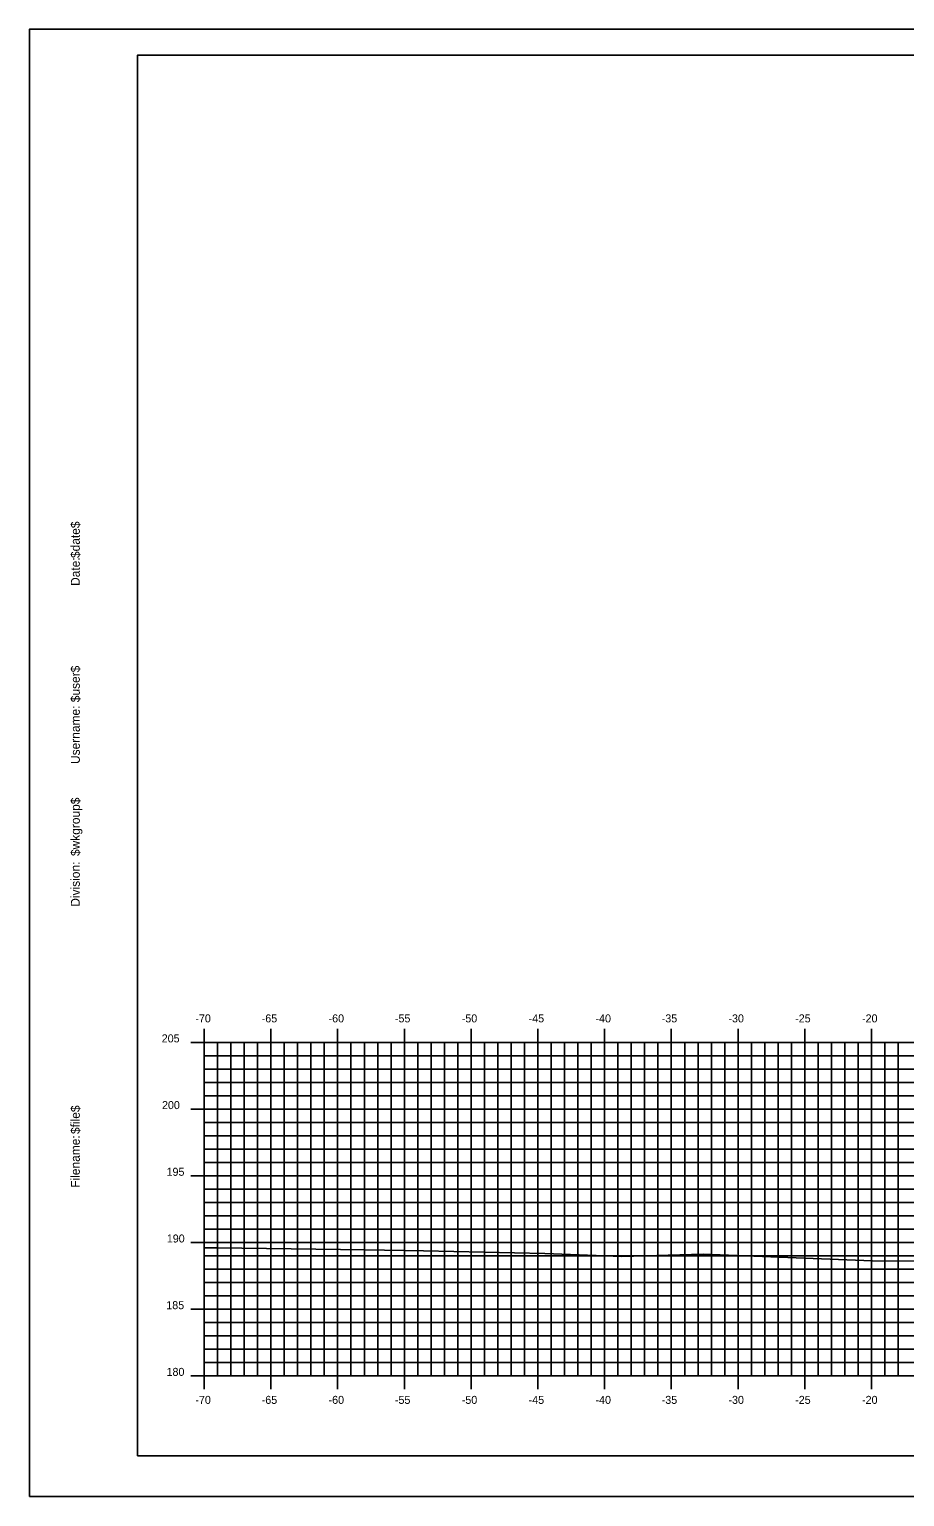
# Model space of a CAD drawing. Extents: x 1724208 to 1724380, y 458501 to 458611.
# Drawn here: x 1724208 to 1724273.5, y 458501.2 to 458611.2 of the extents above; entities that cross this region are included whole.
import ezdxf

# ---------------------------------------------------------------- set-up
doc = ezdxf.new("R2010")
doc.units = 0
for name, color, linetype in [('BORDER', 7, 'Continuous'), ('H_V ANNOTATION', 7, 'Continuous'), ('MAJOR', 7, 'Continuous'), ('MINOR', 7, 'Continuous'), ('PLOT BOUNDARY', 7, 'Continuous'), ('S_Roadway_Centerline', 7, 'Continuous')]:
    doc.layers.add(name, color=color, linetype=linetype)

msp = doc.modelspace()

# ---------------------------------------------------------------- linework, layer by layer
at = {"layer": 'BORDER'}
msp.add_lwpolyline([(1724216.06, 458504.25), (1724376.06, 458504.25), (1724376.06, 458609.25), (1724216.06, 458609.25)], close=True, dxfattribs=at)
at = {"layer": 'MAJOR'}
for p, q in [((1724221.06, 458536.26), (1724221.06, 458535.25)), ((1724226.06, 458536.26), (1724226.06, 458535.25)), ((1724231.06, 458536.26), (1724231.06, 458535.25)), ((1724236.06, 458536.26), (1724236.06, 458535.25)), ((1724241.06, 458536.26), (1724241.06, 458535.25)), ((1724246.06, 458536.26), (1724246.06, 458535.25)), ((1724251.06, 458536.26), (1724251.06, 458535.25)), ((1724256.06, 458536.26), (1724256.06, 458535.25)), ((1724261.06, 458536.26), (1724261.06, 458535.25)), ((1724266.06, 458536.26), (1724266.06, 458535.25)), ((1724271.06, 458536.26), (1724271.06, 458535.25)), ((1724220.05, 458535.25), (1724221.06, 458535.25)), ((1724221.06, 458535.25), (1724361.06, 458535.25)), ((1724221.06, 458510.25), (1724221.06, 458535.25)), ((1724221.06, 458510.25), (1724221.06, 458535.25)), ((1724221.06, 458535.25), (1724361.06, 458535.25)), ((1724226.06, 458510.25), (1724226.06, 458535.25)), ((1724231.06, 458510.25), (1724231.06, 458535.25)), ((1724236.06, 458510.25), (1724236.06, 458535.25)), ((1724241.06, 458510.25), (1724241.06, 458535.25)), ((1724246.06, 458510.25), (1724246.06, 458535.25)), ((1724251.06, 458510.25), (1724251.06, 458535.25)), ((1724256.06, 458510.25), (1724256.06, 458535.25)), ((1724261.06, 458510.25), (1724261.06, 458535.25)), ((1724266.06, 458510.25), (1724266.06, 458535.25)), ((1724271.06, 458510.25), (1724271.06, 458535.25)), ((1724220.05, 458530.25), (1724221.06, 458530.25)), ((1724221.06, 458530.25), (1724361.06, 458530.25)), ((1724220.05, 458525.25), (1724221.06, 458525.25)), ((1724221.06, 458525.25), (1724361.06, 458525.25)), ((1724220.05, 458520.25), (1724221.06, 458520.25)), ((1724221.06, 458520.25), (1724361.06, 458520.25)), ((1724220.05, 458515.25), (1724221.06, 458515.25)), ((1724221.06, 458515.25), (1724361.06, 458515.25)), ((1724220.05, 458510.25), (1724221.06, 458510.25)), ((1724221.06, 458510.25), (1724361.06, 458510.25)), ((1724221.06, 458510.25), (1724361.06, 458510.25)), ((1724221.06, 458509.25), (1724221.06, 458510.25)), ((1724226.06, 458509.25), (1724226.06, 458510.25)), ((1724231.06, 458509.25), (1724231.06, 458510.25)), ((1724236.06, 458509.25), (1724236.06, 458510.25)), ((1724241.06, 458509.25), (1724241.06, 458510.25)), ((1724246.06, 458509.25), (1724246.06, 458510.25)), ((1724251.06, 458509.25), (1724251.06, 458510.25)), ((1724256.06, 458509.25), (1724256.06, 458510.25)), ((1724261.06, 458509.25), (1724261.06, 458510.25)), ((1724266.06, 458509.25), (1724266.06, 458510.25)), ((1724271.06, 458509.25), (1724271.06, 458510.25))]:
    msp.add_line(p, q, dxfattribs=at)
at = {"layer": 'MINOR'}
for p, q in [((1724222.06, 458510.25), (1724222.06, 458535.25)), ((1724223.06, 458510.25), (1724223.06, 458535.25)), ((1724224.06, 458510.25), (1724224.06, 458535.25)), ((1724225.06, 458510.25), (1724225.06, 458535.25)), ((1724227.06, 458510.25), (1724227.06, 458535.25)), ((1724228.06, 458510.25), (1724228.06, 458535.25)), ((1724229.06, 458510.25), (1724229.06, 458535.25)), ((1724230.06, 458510.25), (1724230.06, 458535.25)), ((1724232.06, 458510.25), (1724232.06, 458535.25)), ((1724233.06, 458510.25), (1724233.06, 458535.25)), ((1724234.06, 458510.25), (1724234.06, 458535.25)), ((1724235.06, 458510.25), (1724235.06, 458535.25)), ((1724237.06, 458510.25), (1724237.06, 458535.25)), ((1724238.06, 458510.25), (1724238.06, 458535.25)), ((1724239.06, 458510.25), (1724239.06, 458535.25)), ((1724240.06, 458510.25), (1724240.06, 458535.25)), ((1724242.06, 458510.25), (1724242.06, 458535.25)), ((1724243.06, 458510.25), (1724243.06, 458535.25)), ((1724244.06, 458510.25), (1724244.06, 458535.25)), ((1724245.06, 458510.25), (1724245.06, 458535.25)), ((1724247.06, 458510.25), (1724247.06, 458535.25)), ((1724248.06, 458510.25), (1724248.06, 458535.25)), ((1724249.06, 458510.25), (1724249.06, 458535.25)), ((1724250.06, 458510.25), (1724250.06, 458535.25)), ((1724252.06, 458510.25), (1724252.06, 458535.25)), ((1724253.06, 458510.25), (1724253.06, 458535.25)), ((1724254.06, 458510.25), (1724254.06, 458535.25)), ((1724255.06, 458510.25), (1724255.06, 458535.25)), ((1724257.06, 458510.25), (1724257.06, 458535.25)), ((1724258.06, 458510.25), (1724258.06, 458535.25)), ((1724259.06, 458510.25), (1724259.06, 458535.25)), ((1724260.06, 458510.25), (1724260.06, 458535.25)), ((1724262.06, 458510.25), (1724262.06, 458535.25)), ((1724263.06, 458510.25), (1724263.06, 458535.25)), ((1724264.06, 458510.25), (1724264.06, 458535.25)), ((1724265.06, 458510.25), (1724265.06, 458535.25)), ((1724267.06, 458510.25), (1724267.06, 458535.25)), ((1724268.06, 458510.25), (1724268.06, 458535.25)), ((1724269.06, 458510.25), (1724269.06, 458535.25)), ((1724270.06, 458510.25), (1724270.06, 458535.25)), ((1724272.06, 458510.25), (1724272.06, 458535.25)), ((1724273.06, 458510.25), (1724273.06, 458535.25)), ((1724221.06, 458534.25), (1724361.06, 458534.25)), ((1724221.06, 458534.25), (1724222.06, 458534.25)), ((1724221.06, 458533.25), (1724361.06, 458533.25)), ((1724221.06, 458533.25), (1724222.06, 458533.25)), ((1724221.06, 458532.25), (1724361.06, 458532.25)), ((1724221.06, 458532.25), (1724222.06, 458532.25)), ((1724221.06, 458531.25), (1724361.06, 458531.25)), ((1724221.06, 458531.25), (1724222.06, 458531.25)), ((1724221.06, 458529.25), (1724361.06, 458529.25)), ((1724221.06, 458529.25), (1724222.06, 458529.25)), ((1724221.06, 458528.25), (1724361.06, 458528.25)), ((1724221.06, 458528.25), (1724222.06, 458528.25)), ((1724221.06, 458527.25), (1724361.06, 458527.25)), ((1724221.06, 458527.25), (1724222.06, 458527.25)), ((1724221.06, 458526.25), (1724361.06, 458526.25)), ((1724221.06, 458526.25), (1724222.06, 458526.25)), ((1724221.06, 458524.25), (1724361.06, 458524.25)), ((1724221.06, 458524.25), (1724222.06, 458524.25)), ((1724221.06, 458523.25), (1724361.06, 458523.25)), ((1724221.06, 458523.25), (1724222.06, 458523.25)), ((1724221.06, 458522.25), (1724361.06, 458522.25)), ((1724221.06, 458522.25), (1724222.06, 458522.25)), ((1724221.06, 458521.25), (1724361.06, 458521.25)), ((1724221.06, 458521.25), (1724222.06, 458521.25)), ((1724221.06, 458519.25), (1724361.06, 458519.25)), ((1724221.06, 458519.25), (1724222.06, 458519.25)), ((1724221.06, 458518.25), (1724361.06, 458518.25)), ((1724221.06, 458518.25), (1724222.06, 458518.25)), ((1724221.06, 458517.25), (1724361.06, 458517.25)), ((1724221.06, 458517.25), (1724222.06, 458517.25)), ((1724221.06, 458516.25), (1724361.06, 458516.25)), ((1724221.06, 458516.25), (1724222.06, 458516.25)), ((1724221.06, 458514.25), (1724361.06, 458514.25)), ((1724221.06, 458514.25), (1724222.06, 458514.25)), ((1724221.06, 458513.25), (1724361.06, 458513.25)), ((1724221.06, 458513.25), (1724222.06, 458513.25)), ((1724221.06, 458512.25), (1724361.06, 458512.25)), ((1724221.06, 458512.25), (1724222.06, 458512.25)), ((1724221.06, 458511.25), (1724361.06, 458511.25)), ((1724221.06, 458511.25), (1724222.06, 458511.25))]:
    msp.add_line(p, q, dxfattribs=at)
at = {"layer": 'PLOT BOUNDARY'}
msp.add_lwpolyline([(1724207.96, 458501.2), (1724377.96, 458501.2), (1724377.96, 458611.2), (1724207.96, 458611.2)], close=True, dxfattribs=at)
at = {"layer": 'S_Roadway_Centerline'}
msp.add_lwpolyline([(1724221.06, 458519.86), (1724222.04, 458519.84), (1724233.13, 458519.69), (1724237.5, 458519.63), (1724246.58, 458519.43), (1724252.36, 458519.21), (1724258.45, 458519.37), (1724270.48, 458518.9), (1724271.14, 458518.87), (1724282.01, 458518.79), (1724290.27, 458518.46), (1724306.73, 458518.2), (1724309.81, 458518.04), (1724318.6, 458517.35), (1724329.26, 458517.2), (1724343.8, 458516.42), (1724348.79, 458516.23), (1724361.06, 458515.7)], dxfattribs=at)

# ---------------------------------------------------------------- texts
at = {"layer": 'BORDER'}
for s, p in [('$date$', (1724211.74, 458571.56)), ('Date:', (1724211.74, 458569.47)), ('$user$', (1724211.74, 458560.75)), ('Username:', (1724211.74, 458556.12)), ('$wkgroup$', (1724211.74, 458549.22)), ('Division:', (1724211.74, 458545.42)), ('$file$', (1724211.74, 458528.38)), ('Filename:', (1724211.74, 458524.35))]:
    msp.add_text(s, height=0.67, rotation=90, dxfattribs=at).set_placement(p)
at = {"layer": 'H_V ANNOTATION'}
for s, p in [('-70', (1724220.4, 458536.75)), ('-65', (1724225.37, 458536.75)), ('-60', (1724230.38, 458536.75)), ('-55', (1724235.35, 458536.75)), ('-50', (1724240.36, 458536.75)), ('-45', (1724245.37, 458536.75)), ('-40', (1724250.38, 458536.75)), ('-35', (1724255.34, 458536.75)), ('-30', (1724260.34, 458536.75)), ('-25', (1724265.34, 458536.75)), ('-20', (1724270.35, 458536.75)), ('205', (1724217.88, 458535.25)), ('200', (1724217.9, 458530.25)), ('195', (1724218.24, 458525.25)), ('190', (1724218.26, 458520.25)), ('185', (1724218.22, 458515.25)), ('180', (1724218.24, 458510.25)), ('-70', (1724220.4, 458508.15)), ('-65', (1724225.37, 458508.15)), ('-60', (1724230.38, 458508.15)), ('-55', (1724235.35, 458508.15)), ('-50', (1724240.36, 458508.15)), ('-45', (1724245.37, 458508.15)), ('-40', (1724250.38, 458508.15)), ('-35', (1724255.34, 458508.15)), ('-30', (1724260.34, 458508.15)), ('-25', (1724265.34, 458508.15)), ('-20', (1724270.35, 458508.15))]:
    msp.add_text(s, height=0.6, dxfattribs=at).set_placement(p)
at = {"layer": 'MAJOR'}
msp.add_text('-', height=0.006, dxfattribs=at).set_placement((1724221.05, 458510.25))

doc.saveas('drawing.dxf')
